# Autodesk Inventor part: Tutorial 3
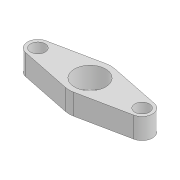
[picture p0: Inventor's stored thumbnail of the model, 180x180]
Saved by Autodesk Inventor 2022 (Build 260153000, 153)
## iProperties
Created: 2021-04
Part Number: Tutorial 3
Material: Generic
Document SubType Name: Modeling
Designer: ASUS Laptop
Density: 1 g/cm^3
Appearance: Default
Author: ASUS Laptop
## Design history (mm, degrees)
sketch "Sketch1"
  geometry: L1 (26, -4.899)-(2, -9.798); L2 (-26, -4.899)-(-2, -9.798); L3 (-26, 4.899)-(-2, 9.798); L4 (26, 4.899)-(2, 9.798); L5 (0, 0)-(-33.69, 0); L6 (0, 0)-(0, -33.352); C1 r 7.5 at (0, 0); C2 r 3.5 at (25, 0); C3 r 3.5 at (-25, 0); A1 r 5 centre (-25, 0) between (-26, 4.899) and (-26, -4.899); A2 r 5 centre (25, 0) between (26, -4.899) and (26, 4.899); A3 r 10 centre (0, 0) between (-2, -9.798) and (2, -9.798); A4 r 10 centre (0, 0) between (2, 9.798) and (-2, 9.798); 1 further point
  constraints: 12 end point, 8 point on circle, 8 tangent, 7 centre point, 4 coincident, 2 equal radius, 2 point on line, 1 horizontal, 1 vertical, 2 other
  dimensions: "d0" = 10 radius of A3; "d1" = 5 radius of A2; "d2" = 50 distance of A1.centre A2.centre; "d3" = 7 diameter of C2; "d4" = 15 diameter of C1
extrude "Extrusion1" new body sketch "Sketch1" distance "d5" = 10; taper "d6" = 0 deg
body "Solid1"
